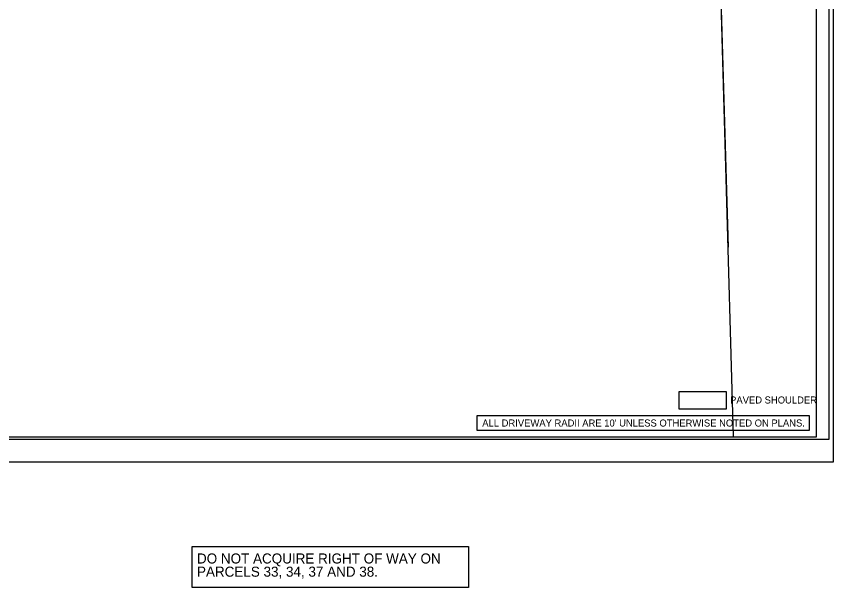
# Model space of a CAD drawing. Extents: x 1757668 to 1759700, y 736393 to 737693.
# Drawn here: x 1758684 to 1759496, y 736393 to 736960 of the extents above; entities that cross this region are included whole.
import ezdxf

# ---------------------------------------------------------------- set-up
doc = ezdxf.new("R2010")
doc.units = 0
for name, color, linetype in [('Matchline', 7, 'Continuous'), ('Old_Level_40', 7, 'Continuous'), ('Prop DSN Text', 7, 'Continuous'), ('Prop Grid Mask', 7, 'Continuous'), ('Prop Shade Light', 7, 'Continuous'), ('Scratch_Level_3', 7, 'Continuous'), ('Sheet Border Standard 30in CELL', 7, 'Continuous'), ('Sheet Clip Boundary CELL', 7, 'Continuous'), ('Sheet Cutting Line CELL', 7, 'Continuous'), ('Sheet Plot Border Inside CELL', 7, 'Continuous'), ('Sheet Plot Border Outside CELL', 7, 'Continuous')]:
    doc.layers.add(name, color=color, linetype=linetype)

msp = doc.modelspace()

# ---------------------------------------------------------------- linework, layer by layer
at = {"layer": 'Matchline'}
msp.add_line((1759375.5, 737296.74), (1759391.56, 736730.93), dxfattribs=at)
at = {"layer": 'Old_Level_40'}
msp.add_lwpolyline([(1759390.05, 736587.22), (1759342.73, 736587.22), (1759342.73, 736570.28), (1759390.05, 736570.28), (1759390.05, 736587.22)], dxfattribs=at)
msp.add_lwpolyline([(1759390.05, 736587.22), (1759342.73, 736587.22), (1759342.73, 736570.28), (1759390.05, 736570.28)], close=True, dxfattribs=at)
at = {"layer": 'Prop Grid Mask'}
for points in [[(1759142.15, 736563.79), (1759472.07, 736563.79), (1759472.07, 736548.79), (1759142.15, 736548.79)], [(1758858.93, 736433.83), (1759133.56, 736433.83), (1759133.56, 736392.83), (1758858.93, 736392.83)]]:
    msp.add_lwpolyline(points, close=True, dxfattribs=at)
at = {"layer": 'Prop Shade Light'}
msp.add_lwpolyline([(1759390.05, 736587.22), (1759342.73, 736587.22), (1759342.73, 736570.28), (1759390.05, 736570.28), (1759390.05, 736587.22)], dxfattribs=at)
msp.add_lwpolyline([(1759390.05, 736587.22), (1759342.73, 736587.22), (1759342.73, 736570.28), (1759390.05, 736570.28)], close=True, dxfattribs=at)
at = {"layer": 'Scratch_Level_3'}
msp.add_lwpolyline([(1757979.5, 736542.73), (1759479.49, 736542.73), (1759479.49, 737359.59), (1759279.44, 737359.59), (1759279.44, 737592.73), (1757979.5, 737592.73)], close=True, dxfattribs=at)
at = {"layer": 'Sheet Border Standard 30in CELL'}
msp.add_lwpolyline([(1759479.49, 737592.73), (1757979.49, 737592.73), (1757979.49, 736542.73), (1759479.49, 736542.73)], close=True, dxfattribs=at)
at = {"layer": 'Sheet Clip Boundary CELL'}
msp.add_lwpolyline([(1758096.38, 736542.73), (1759396.91, 736542.73), (1759374.07, 737347.1), (1759279.44, 737347.1), (1759279.44, 737592.73), (1758066.57, 737592.73)], close=True, dxfattribs=at)
msp.add_lwpolyline([(1758096.38, 736542.73), (1759396.91, 736542.73), (1759374.07, 737347.1), (1759279.44, 737347.1), (1759279.44, 737592.73), (1758066.57, 737592.73)], close=True, dxfattribs=at)
at = {"layer": 'Sheet Cutting Line CELL'}
msp.add_line((1757812.49, 736517.73), (1759496.49, 736517.73), dxfattribs=at)
at = {"layer": 'Sheet Plot Border Inside CELL'}
msp.add_lwpolyline([(1759491.99, 737595.28), (1757825.49, 737595.28), (1757825.49, 736540.18), (1759491.99, 736540.18)], close=True, dxfattribs=at)
at = {"layer": 'Sheet Plot Border Outside CELL'}
msp.add_lwpolyline([(1759496.49, 737617.73), (1757812.49, 737617.73), (1757812.49, 736517.73), (1759496.49, 736517.73)], close=True, dxfattribs=at)

# ---------------------------------------------------------------- texts
at = {"layer": 'Prop DSN Text'}
msp.add_text('PAVED SHOULDER', height=7, dxfattribs=at).set_placement((1759393.57, 736575.66))
for s, height, p in [("ALL DRIVEWAY RADII ARE 10' UNLESS OTHERWISE NOTED ON PLANS.", 7, (1759147.29, 736552.79)), ('DO NOT ACQUIRE RIGHT OF WAY ON ', 10, (1758863.8, 736416.79)), ('PARCELS 33, 34, 37 AND 38.', 10, (1758863.8, 736403.68))]:
    msp.add_text(s, height=height, rotation=359.9997, dxfattribs=at).set_placement(p)

doc.saveas('drawing.dxf')
